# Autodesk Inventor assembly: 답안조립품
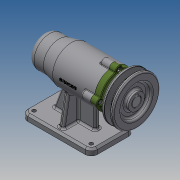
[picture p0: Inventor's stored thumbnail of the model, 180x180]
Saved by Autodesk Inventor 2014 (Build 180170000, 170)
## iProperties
Created: 2019-07
Part Number: 답안조립품
Document SubType Name: Assembly
Designer: kb542-7
Author: kb542-7
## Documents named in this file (12)
- C:\Users\kb542-7\Desktop\490704V1059\답안조립품.iam
- C:\Users\kb542-7\Desktop\490704V1059\본체.ipt
- C:\Users\kb542-7\Desktop\490704V1059\V벨트풀리.ipt
- C:\Users\kb542-7\Desktop\490704V1059\멈춤나사 M3.ipt
- C:\Users\kb542-7\Desktop\490704V1059\베어링 6004.ipt
- C:\Users\kb542-7\Desktop\490704V1059\베어링 51202.ipt
- C:\Users\kb542-7\Desktop\490704V1059\볼트 M4.ipt
- C:\Users\kb542-7\Desktop\490704V1059\어댑터슬리브.ipt
- C:\Users\kb542-7\Desktop\490704V1059\오일 실.ipt
- C:\Users\kb542-7\Desktop\490704V1059\축.ipt
- C:\Users\kb542-7\Desktop\490704V1059\커버.ipt
- C:\Users\kb542-7\Desktop\490704V1059\키 5 x 5 x 16.ipt
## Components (1 placed, 1 different names)
1. V벨트풀리:1
